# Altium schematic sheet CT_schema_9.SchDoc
size 147 x 119 mm
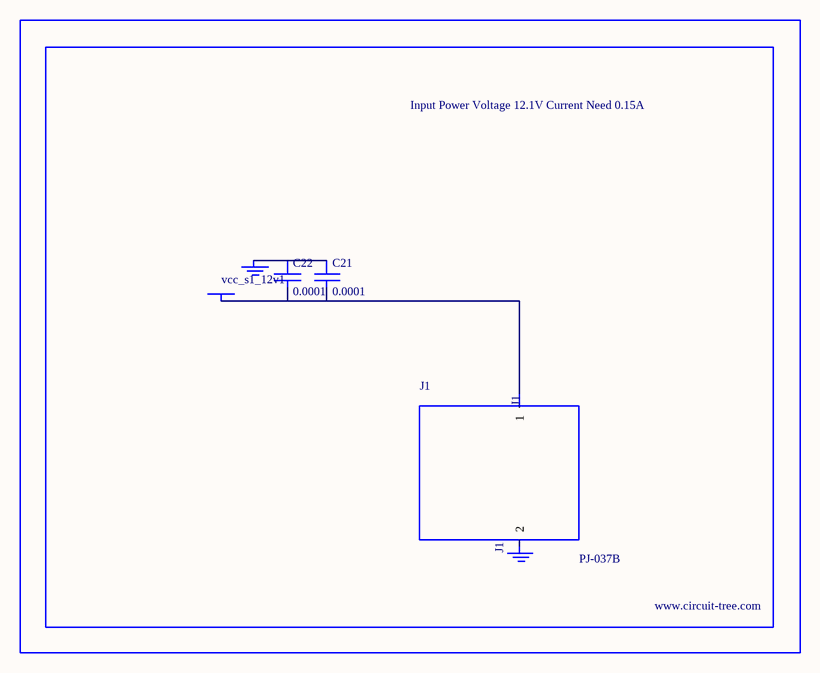
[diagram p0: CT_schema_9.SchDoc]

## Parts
BORDER8  (no value)
C21  0.0001  [EXV-9H]
C22  0.0001  [EXV-9H]
GND_INSTANCE_8_0  (no value)
GND_INSTANCE_8_1  (no value)
J1  PJ-037B  [PJ-037B_PACKAGE]
POWER_INSTANCE_8_0  vcc_s1_12v1

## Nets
NetC21_1: C21.1 C22.1 GND_INSTANCE_8_0.0(GND)
NetC21_2: C21.2 C22.2 J1.1 POWER_INSTANCE_8_0.0(PWR)

Not connected (* = marked no-connect by the designer): GND_INSTANCE_8_1 0(GND); J1 2

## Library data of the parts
BORDER8 = BORDER_PAGE8
C21 C22 = EDK107M035A9HAA
GND_INSTANCE_8_0 GND_INSTANCE_8_1 = GND
POWER_INSTANCE_8_0 = PWR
